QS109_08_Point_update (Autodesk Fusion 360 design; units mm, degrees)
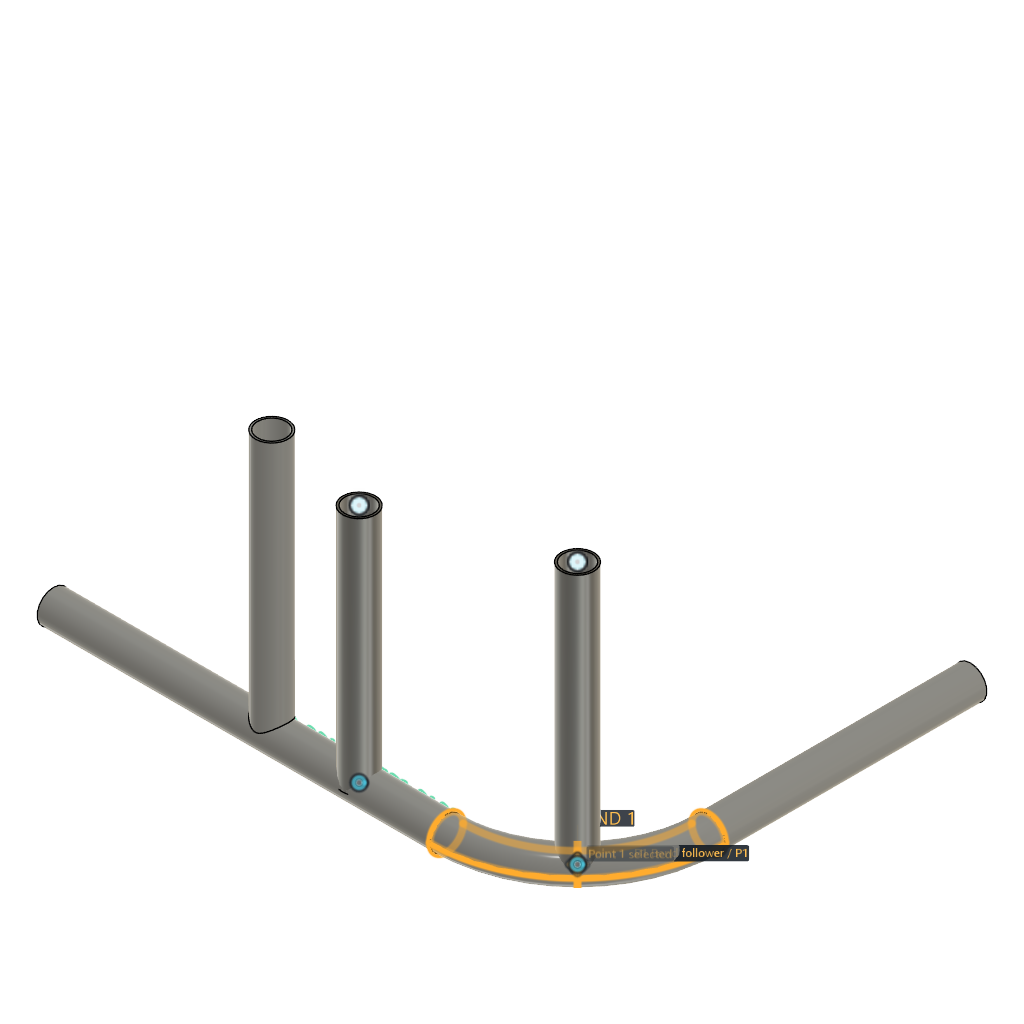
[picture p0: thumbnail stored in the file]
description: Part Number
part number: 2026-10-26-11-38-19-526
parameter "OD_DEMO_ONLY_1_5_x_095_R6" = 38.1
parameter "Wall_DEMO_ONLY_1_5_x_095_R6" = 2.413
base_feature "Base Feature" bodies "H1 Bent host", "I1 Imported coped brace"
sketch "Tube points" plane through (0, 0, 0) normal (0, 0, 1) x axis (1, 0, 0)
sketch "TubePoints" plane through (0, 0, 0) normal (0, 0, 1) x axis (1, 0, 0)
work_plane "WorkPlane1" ExtraOffset 0
sketch "Sketch3" plane through (564.9631, 44.6369, 0) normal (0, 0, 1) x axis (0, 1, 0)
  circle C1 centre (0, 0) radius 19.05
  circle C2 centre (0, 0) radius 16.637
sketch "TubePoints (1)" plane through (0, 0, 0) normal (0, 0, 1) x axis (1, 0, 0)
work_plane "WorkPlane2" ExtraOffset 0
sketch "Sketch5" plane through (355.6, 0, 0) normal (0, 0, 1) x axis (0, 1, 0)
  circle C1 centre (0, 0) radius 19.05
  circle C2 centre (0, 0) radius 16.637
sketch "TubePoints (2)" plane through (0, 0, 0) normal (0, 0, 1) x axis (1, 0, 0)
work_plane "WorkPlane3" ExtraOffset 0
sketch "Sketch7" plane through (564.9631, 44.6369, 0) normal (0, 0, 1) x axis (0, 1, 0)
  circle C1 centre (0, 0) radius 19.05
  circle C2 centre (0, 0) radius 16.637
  dimension "d21" diameter C1 = 38.1 (= "OD_DEMO_ONLY_1_5_x_095_R6")
  dimension "d22" diameter C2 = 33.274 (= "OD_DEMO_ONLY_1_5_x_095_R6 - 2 * Wall_DEMO_ONLY_1_5_x_095_R6")
sweep "Sweep3" sketch "Sketch7" TwistAngle 0 TaperAngle 0 bodies "B1 Bend follower"
sketch "TubePoints (3)" plane through (0, 0, 0) normal (0, 0, 1) x axis (1, 0, 0)
work_plane "WorkPlane4" ExtraOffset 0
sketch "Sketch9" plane through (355.6, 0, 0) normal (0, 0, 1) x axis (0, 1, 0)
  circle C1 centre (0, 0) radius 19.05
  circle C2 centre (0, 0) radius 16.637
  dimension "d31" diameter C1 = 38.1 (= "OD_DEMO_ONLY_1_5_x_095_R6")
  dimension "d32" diameter C2 = 33.274 (= "OD_DEMO_ONLY_1_5_x_095_R6 - 2 * Wall_DEMO_ONLY_1_5_x_095_R6")
sweep "Sweep4" sketch "Sketch9" TwistAngle 0 TaperAngle 0 bodies "B2 Straight joint"
named bodies: "H1 Bent host", "I1 Imported coped brace", "B1 Bend follower", "B2 Straight joint"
